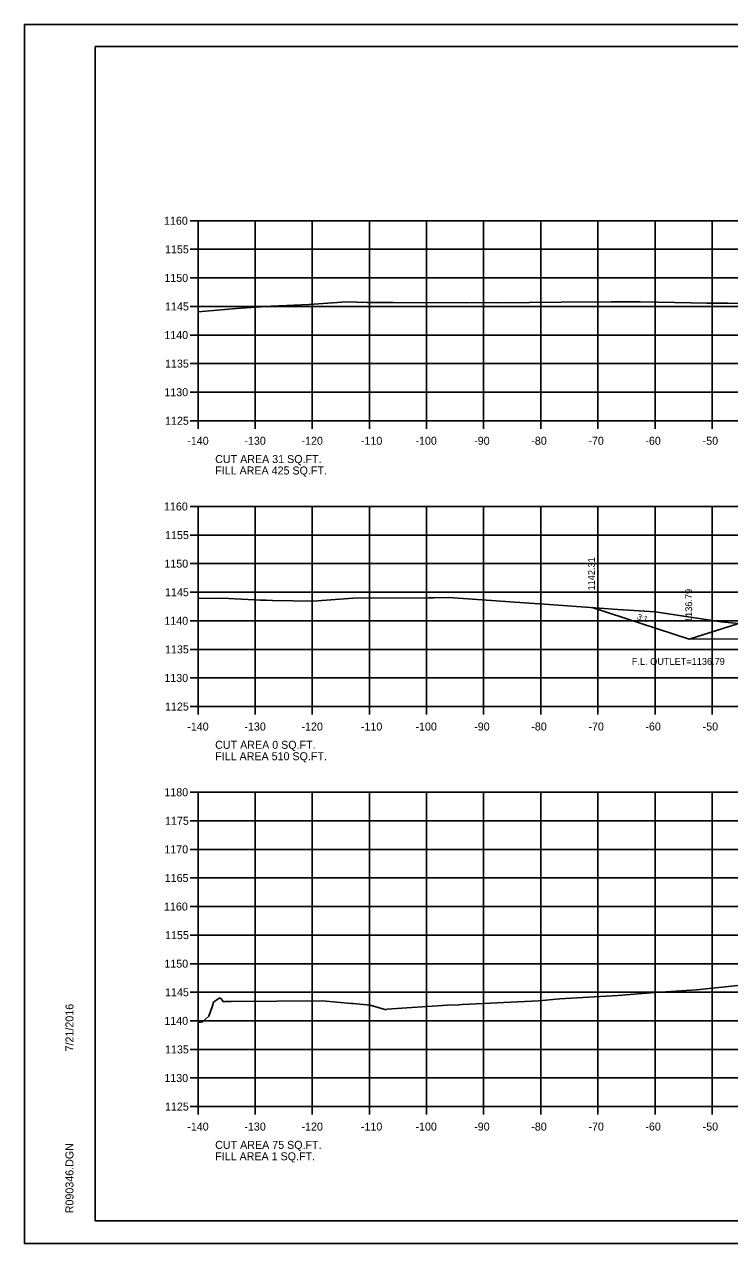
# Model space of a CAD drawing. Extents: x 1368971 to 1374497, y 378717 to 381839.
# Drawn here: x 1374163.9 to 1374287.4, y 380805.4 to 381018.8 of the extents above; entities that cross this region are included whole.
import ezdxf

# ---------------------------------------------------------------- set-up
doc = ezdxf.new("R2010")
doc.units = 0
for name, color, linetype in [('R_Axis', 7, 'Continuous'), ('R_Axis Annot', 7, 'Continuous'), ('R_Border', 7, 'Continuous'), ('R_Exist Surface', 7, 'Continuous'), ('R_Fin Surface', 7, 'Continuous'), ('R_Grid', 7, 'Continuous'), ('R_No Plot', 7, 'Continuous'), ('R_Water', 7, 'Continuous'), ('R_Water Annot', 7, 'Continuous'), ('R_Xsect Elev', 7, 'Continuous'), ('R_Xsect Slope', 7, 'Continuous')]:
    doc.layers.add(name, color=color, linetype=linetype)

msp = doc.modelspace()

# ---------------------------------------------------------------- linework, layer by layer
at = {"layer": 'R_Axis'}
for p, q in [((1374192.94, 380984.4), (1374194.34, 380984.4)), ((1374194.34, 380949.4), (1374194.34, 380984.4)), ((1374192.94, 380979.4), (1374194.34, 380979.4)), ((1374192.94, 380974.4), (1374194.34, 380974.4)), ((1374192.94, 380969.4), (1374194.34, 380969.4)), ((1374192.94, 380964.4), (1374194.34, 380964.4)), ((1374192.94, 380959.4), (1374194.34, 380959.4)), ((1374192.94, 380954.4), (1374194.34, 380954.4)), ((1374192.94, 380949.4), (1374194.34, 380949.4)), ((1374194.34, 380949.4), (1374474.34, 380949.4)), ((1374194.34, 380948), (1374194.34, 380949.4)), ((1374204.34, 380948), (1374204.34, 380949.4)), ((1374214.34, 380948), (1374214.34, 380949.4)), ((1374224.34, 380948), (1374224.34, 380949.4)), ((1374234.34, 380948), (1374234.34, 380949.4)), ((1374244.34, 380948), (1374244.34, 380949.4)), ((1374254.34, 380948), (1374254.34, 380949.4)), ((1374264.34, 380948), (1374264.34, 380949.4)), ((1374274.34, 380948), (1374274.34, 380949.4)), ((1374284.34, 380948), (1374284.34, 380949.4)), ((1374192.94, 380934.4), (1374194.34, 380934.4)), ((1374194.34, 380899.4), (1374194.34, 380934.4)), ((1374192.94, 380929.4), (1374194.34, 380929.4)), ((1374192.94, 380924.4), (1374194.34, 380924.4)), ((1374192.94, 380919.4), (1374194.34, 380919.4)), ((1374192.94, 380914.4), (1374194.34, 380914.4)), ((1374192.94, 380909.4), (1374194.34, 380909.4)), ((1374192.94, 380904.4), (1374194.34, 380904.4)), ((1374192.94, 380899.4), (1374194.34, 380899.4)), ((1374194.34, 380899.4), (1374474.34, 380899.4)), ((1374194.34, 380898), (1374194.34, 380899.4)), ((1374204.34, 380898), (1374204.34, 380899.4)), ((1374214.34, 380898), (1374214.34, 380899.4)), ((1374224.34, 380898), (1374224.34, 380899.4)), ((1374234.34, 380898), (1374234.34, 380899.4)), ((1374244.34, 380898), (1374244.34, 380899.4)), ((1374254.34, 380898), (1374254.34, 380899.4)), ((1374264.34, 380898), (1374264.34, 380899.4)), ((1374274.34, 380898), (1374274.34, 380899.4)), ((1374284.34, 380898), (1374284.34, 380899.4)), ((1374192.94, 380884.4), (1374194.34, 380884.4)), ((1374194.34, 380829.4), (1374194.34, 380884.4)), ((1374192.94, 380879.4), (1374194.34, 380879.4)), ((1374192.94, 380874.4), (1374194.34, 380874.4)), ((1374192.94, 380869.4), (1374194.34, 380869.4)), ((1374192.94, 380864.4), (1374194.34, 380864.4)), ((1374192.94, 380859.4), (1374194.34, 380859.4)), ((1374192.94, 380854.4), (1374194.34, 380854.4)), ((1374192.94, 380849.4), (1374194.34, 380849.4)), ((1374192.94, 380844.4), (1374194.34, 380844.4)), ((1374192.94, 380839.4), (1374194.34, 380839.4)), ((1374192.94, 380834.4), (1374194.34, 380834.4)), ((1374192.94, 380829.4), (1374194.34, 380829.4)), ((1374194.34, 380829.4), (1374474.34, 380829.4)), ((1374194.34, 380828), (1374194.34, 380829.4)), ((1374204.34, 380828), (1374204.34, 380829.4)), ((1374214.34, 380828), (1374214.34, 380829.4)), ((1374224.34, 380828), (1374224.34, 380829.4)), ((1374234.34, 380828), (1374234.34, 380829.4)), ((1374244.34, 380828), (1374244.34, 380829.4)), ((1374254.34, 380828), (1374254.34, 380829.4)), ((1374264.34, 380828), (1374264.34, 380829.4)), ((1374274.34, 380828), (1374274.34, 380829.4)), ((1374284.34, 380828), (1374284.34, 380829.4))]:
    msp.add_line(p, q, dxfattribs=at)
at = {"layer": 'R_Border'}
for p, q in [((1374176.34, 381014.86), (1374492.52, 381014.86)), ((1374176.34, 380809.4), (1374176.34, 381014.86)), ((1374176.34, 380809.4), (1374176.34, 380809.4)), ((1374492.52, 380809.4), (1374176.34, 380809.4))]:
    msp.add_line(p, q, dxfattribs=at)
at = {"layer": 'R_Exist Surface'}
for points in [[(1374194.34, 380968.46), (1374195.69, 380968.55), (1374201.03, 380969.06), (1374207.13, 380969.48), (1374213.82, 380969.72), (1374220.33, 380970.19), (1374223.97, 380970.11), (1374228.51, 380970.08), (1374241.39, 380970.06), (1374243.67, 380970.07), (1374246.84, 380970.06), (1374257.9, 380970.14), (1374266.68, 380970.19), (1374271.75, 380970.22), (1374277.79, 380970.07), (1374283.4, 380970), (1374287.16, 380969.95), (1374299.62, 380969.8)], [(1374194.34, 380918.29), (1374198.64, 380918.38), (1374205.3, 380918.03), (1374205.99, 380918), (1374206.25, 380918), (1374207.37, 380917.97), (1374214.5, 380917.83), (1374221.43, 380918.38), (1374234.68, 380918.43), (1374235.63, 380918.42), (1374238.25, 380918.45), (1374252.28, 380917.49), (1374255, 380917.29), (1374267.83, 380916.4), (1374274.35, 380915.94), (1374285.9, 380914.21), (1374291.4, 380913.72)], [(1374194.34, 380844.11), (1374195.12, 380844.2), (1374196.25, 380845.23), (1374196.86, 380847), (1374197.06, 380847.67), (1374198.04, 380848.38), (1374198.26, 380848.34), (1374198.32, 380848.29), (1374198.82, 380847.72), (1374199.05, 380847.77), (1374200.16, 380847.78), (1374216.11, 380847.88), (1374221.17, 380847.44), (1374221.52, 380847.43), (1374224.45, 380847.17), (1374227.27, 380846.33), (1374227.4, 380846.42), (1374237.94, 380847.12), (1374237.98, 380847.12), (1374239.98, 380847.2), (1374240.58, 380847.25), (1374253.97, 380847.93), (1374257.68, 380848.25), (1374267.81, 380848.83), (1374273.53, 380849.32), (1374281.59, 380849.82), (1374304.47, 380852.2)]]:
    msp.add_lwpolyline(points, dxfattribs=at)
at = {"layer": 'R_Fin Surface'}
for p, q in [((1374306.39, 380919.53), (1374280.34, 380911.19)), ((1374280.34, 380911.19), (1374263.31, 380916.71))]:
    msp.add_line(p, q, dxfattribs=at)
at = {"layer": 'R_Grid'}
for p, q in [((1374194.34, 380984.4), (1374474.34, 380984.4)), ((1374194.34, 380949.4), (1374194.34, 380984.4)), ((1374204.34, 380949.4), (1374204.34, 380984.4)), ((1374214.34, 380949.4), (1374214.34, 380984.4)), ((1374224.34, 380949.4), (1374224.34, 380984.4)), ((1374234.34, 380949.4), (1374234.34, 380984.4)), ((1374244.34, 380949.4), (1374244.34, 380984.4)), ((1374254.34, 380949.4), (1374254.34, 380984.4)), ((1374264.34, 380949.4), (1374264.34, 380984.4)), ((1374274.34, 380949.4), (1374274.34, 380984.4)), ((1374284.34, 380949.4), (1374284.34, 380984.4)), ((1374194.34, 380979.4), (1374474.34, 380979.4)), ((1374194.34, 380974.4), (1374474.34, 380974.4)), ((1374194.34, 380969.4), (1374474.34, 380969.4)), ((1374194.34, 380964.4), (1374474.34, 380964.4)), ((1374194.34, 380959.4), (1374474.34, 380959.4)), ((1374194.34, 380954.4), (1374474.34, 380954.4)), ((1374194.34, 380949.4), (1374474.34, 380949.4)), ((1374194.34, 380934.4), (1374474.34, 380934.4)), ((1374194.34, 380899.4), (1374194.34, 380934.4)), ((1374204.34, 380899.4), (1374204.34, 380934.4)), ((1374214.34, 380899.4), (1374214.34, 380934.4)), ((1374224.34, 380899.4), (1374224.34, 380934.4)), ((1374234.34, 380899.4), (1374234.34, 380934.4)), ((1374244.34, 380899.4), (1374244.34, 380934.4)), ((1374254.34, 380899.4), (1374254.34, 380934.4)), ((1374264.34, 380899.4), (1374264.34, 380934.4)), ((1374274.34, 380899.4), (1374274.34, 380934.4)), ((1374284.34, 380899.4), (1374284.34, 380934.4)), ((1374194.34, 380929.4), (1374474.34, 380929.4)), ((1374194.34, 380924.4), (1374474.34, 380924.4)), ((1374194.34, 380919.4), (1374474.34, 380919.4)), ((1374194.34, 380914.4), (1374474.34, 380914.4)), ((1374194.34, 380909.4), (1374474.34, 380909.4)), ((1374194.34, 380904.4), (1374474.34, 380904.4)), ((1374194.34, 380899.4), (1374474.34, 380899.4)), ((1374194.34, 380884.4), (1374474.34, 380884.4)), ((1374194.34, 380829.4), (1374194.34, 380884.4)), ((1374204.34, 380829.4), (1374204.34, 380884.4)), ((1374214.34, 380829.4), (1374214.34, 380884.4)), ((1374224.34, 380829.4), (1374224.34, 380884.4)), ((1374234.34, 380829.4), (1374234.34, 380884.4)), ((1374244.34, 380829.4), (1374244.34, 380884.4)), ((1374254.34, 380829.4), (1374254.34, 380884.4)), ((1374264.34, 380829.4), (1374264.34, 380884.4)), ((1374274.34, 380829.4), (1374274.34, 380884.4)), ((1374284.34, 380829.4), (1374284.34, 380884.4)), ((1374194.34, 380879.4), (1374474.34, 380879.4)), ((1374194.34, 380874.4), (1374474.34, 380874.4)), ((1374194.34, 380869.4), (1374474.34, 380869.4)), ((1374194.34, 380864.4), (1374474.34, 380864.4)), ((1374194.34, 380859.4), (1374474.34, 380859.4)), ((1374194.34, 380854.4), (1374474.34, 380854.4)), ((1374194.34, 380849.4), (1374474.34, 380849.4)), ((1374194.34, 380844.4), (1374474.34, 380844.4)), ((1374194.34, 380839.4), (1374474.34, 380839.4)), ((1374194.34, 380834.4), (1374474.34, 380834.4)), ((1374194.34, 380829.4), (1374474.34, 380829.4))]:
    msp.add_line(p, q, dxfattribs=at)
at = {"layer": 'R_No Plot'}
for p, q in [((1374163.94, 381018.76), (1374497.27, 381018.76)), ((1374163.94, 380805.42), (1374497.27, 380805.42))]:
    msp.add_line(p, q, dxfattribs=at)
for points in [[(1374163.93, 381018.76), (1374497.27, 381018.76), (1374497.27, 380805.42), (1374163.93, 380805.42)], [(1374410.26, 381014.86), (1374410.26, 381004.98), (1374445.99, 381004.98), (1374445.99, 381002.06), (1374469.19, 381002.06), (1374469.19, 380978.85), (1374492.52, 380978.85), (1374492.52, 380809.4), (1374176.34, 380809.4), (1374176.34, 381014.86)]]:
    msp.add_lwpolyline(points, close=True, dxfattribs=at)
at = {"layer": 'R_Water'}
msp.add_line((1374304.35, 380911.24), (1374280.34, 380911.19), dxfattribs=at)

# ---------------------------------------------------------------- texts
at = {"layer": 'R_Axis'}
for p in [(1374194.34, 380949.4), (1374194.34, 380899.4), (1374194.34, 380829.4)]:
    msp.add_text('-', height=0.0001, dxfattribs=at).set_placement(p)
at = {"layer": 'R_Axis Annot'}
for s, p in [('1160', (1374188.38, 380983.7)), ('1155', (1374188.56, 380978.7)), ('1150', (1374188.44, 380973.7)), ('1145', (1374188.56, 380968.7)), ('1140', (1374188.44, 380963.7)), ('1135', (1374188.56, 380958.7)), ('1130', (1374188.44, 380953.7)), ('1125', (1374188.56, 380948.7)), ('-140', (1374192.45, 380945.2)), ('-130', (1374202.45, 380945.2)), ('-120', (1374212.45, 380945.2)), ('-110', (1374222.85, 380945.2)), ('-100', (1374232.4, 380945.2)), ('-90', (1374242.68, 380945.2)), ('-80', (1374252.68, 380945.2)), ('-70', (1374262.68, 380945.2)), ('-60', (1374272.65, 380945.2)), ('-50', (1374282.68, 380945.2)), ('CUT AREA 31 SQ.FT.', (1374197.34, 380942)), ('FILL AREA 425 SQ.FT.', (1374197.34, 380940)), ('1160', (1374188.38, 380933.7)), ('1155', (1374188.56, 380928.7)), ('1150', (1374188.44, 380923.7)), ('1145', (1374188.56, 380918.7)), ('1140', (1374188.44, 380913.7)), ('1135', (1374188.56, 380908.7)), ('1130', (1374188.44, 380903.7)), ('1125', (1374188.56, 380898.7)), ('-140', (1374192.45, 380895.2)), ('-130', (1374202.45, 380895.2)), ('-120', (1374212.45, 380895.2)), ('-110', (1374222.85, 380895.2)), ('-100', (1374232.4, 380895.2)), ('-90', (1374242.68, 380895.2)), ('-80', (1374252.68, 380895.2)), ('-70', (1374262.68, 380895.2)), ('-60', (1374272.65, 380895.2)), ('-50', (1374282.68, 380895.2)), ('CUT AREA 0 SQ.FT.', (1374197.34, 380892)), ('FILL AREA 510 SQ.FT.', (1374197.34, 380890)), ('1180', (1374188.44, 380883.7)), ('1175', (1374188.56, 380878.7)), ('1170', (1374188.44, 380873.7)), ('1165', (1374188.5, 380868.7)), ('1160', (1374188.38, 380863.7)), ('1155', (1374188.56, 380858.7)), ('1150', (1374188.44, 380853.7)), ('1145', (1374188.56, 380848.7)), ('1140', (1374188.44, 380843.7)), ('1135', (1374188.56, 380838.7)), ('1130', (1374188.44, 380833.7)), ('1125', (1374188.56, 380828.7)), ('-140', (1374192.45, 380825.2)), ('-130', (1374202.45, 380825.2)), ('-120', (1374212.45, 380825.2)), ('-110', (1374222.85, 380825.2)), ('-100', (1374232.4, 380825.2)), ('-90', (1374242.68, 380825.2)), ('-80', (1374252.68, 380825.2)), ('-70', (1374262.68, 380825.2)), ('-60', (1374272.65, 380825.2)), ('-50', (1374282.68, 380825.2)), ('CUT AREA 75 SQ.FT.', (1374197.34, 380822)), ('FILL AREA 1 SQ.FT.', (1374197.34, 380820))]:
    msp.add_text(s, height=1.4, dxfattribs=at).set_placement(p)
at = {"layer": 'R_Border'}
for s, p in [('7/21/2016', (1374172.53, 380839.05)), ('R090346.DGN', (1374172.53, 380810.73))]:
    msp.add_text(s, height=1.4, rotation=90, dxfattribs=at).set_placement(p)
at = {"layer": 'R_Water Annot'}
msp.add_text('F.L. OUTLET=1136.79', height=1.2, dxfattribs=at).set_placement((1374270.28, 380906.69))
msp.add_text('F.L. OUTLET=1136.79', height=1.2, dxfattribs=at).set_placement((1374270.28, 380906.69))
at = {"layer": 'R_Xsect Elev'}
for s, p in [('1142.31', (1374263.81, 380919.71)), ('1136.79', (1374280.84, 380914.19))]:
    msp.add_text(s, height=1.2, rotation=90, dxfattribs=at).set_placement(p)
at = {"layer": 'R_Xsect Slope'}
msp.add_text('3:1', height=1, rotation=342.0537, dxfattribs=at).set_placement((1374271.12, 380914.71))

doc.saveas('drawing.dxf')
